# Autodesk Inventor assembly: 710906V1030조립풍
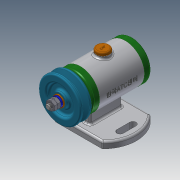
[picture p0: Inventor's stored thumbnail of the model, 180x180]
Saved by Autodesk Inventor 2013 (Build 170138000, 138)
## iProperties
Created: 2021-09
Part Number: 710906V1030조립풍
Document SubType Name: Assembly
Designer: kum
Author: kum
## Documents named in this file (14)
- C:\Users\kum\Desktop\710906V1030\710906V1030조립풍.iam
- C:\Users\kum\Desktop\710906V1030\본체.ipt
- C:\Users\kum\Desktop\710906V1030\캡.ipt
- C:\Users\kum\Desktop\710906V1030\V벨트풀리.ipt
- C:\Users\kum\Desktop\710906V1030\뒤커버.ipt
- C:\Users\kum\Desktop\710906V1030\베어링 15x32x9.ipt
- C:\Users\kum\Desktop\710906V1030\스프링와셔 8.ipt
- C:\Users\kum\Desktop\710906V1030\앞커버.ipt
- C:\Users\kum\Desktop\710906V1030\오일 실 15x25x7.ipt
- C:\Users\kum\Desktop\710906V1030\와셔 8x17.ipt
- C:\Users\kum\Desktop\710906V1030\축.ipt
- C:\Users\kum\Desktop\710906V1030\키 3x3.ipt
- C:\Users\kum\Desktop\710906V1030\너트 M8.ipt
- C:\Users\kum\Desktop\710906V1030\볼트 M4x12.ipt
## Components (1 placed, 1 different names)
1. V벨트풀리:1
